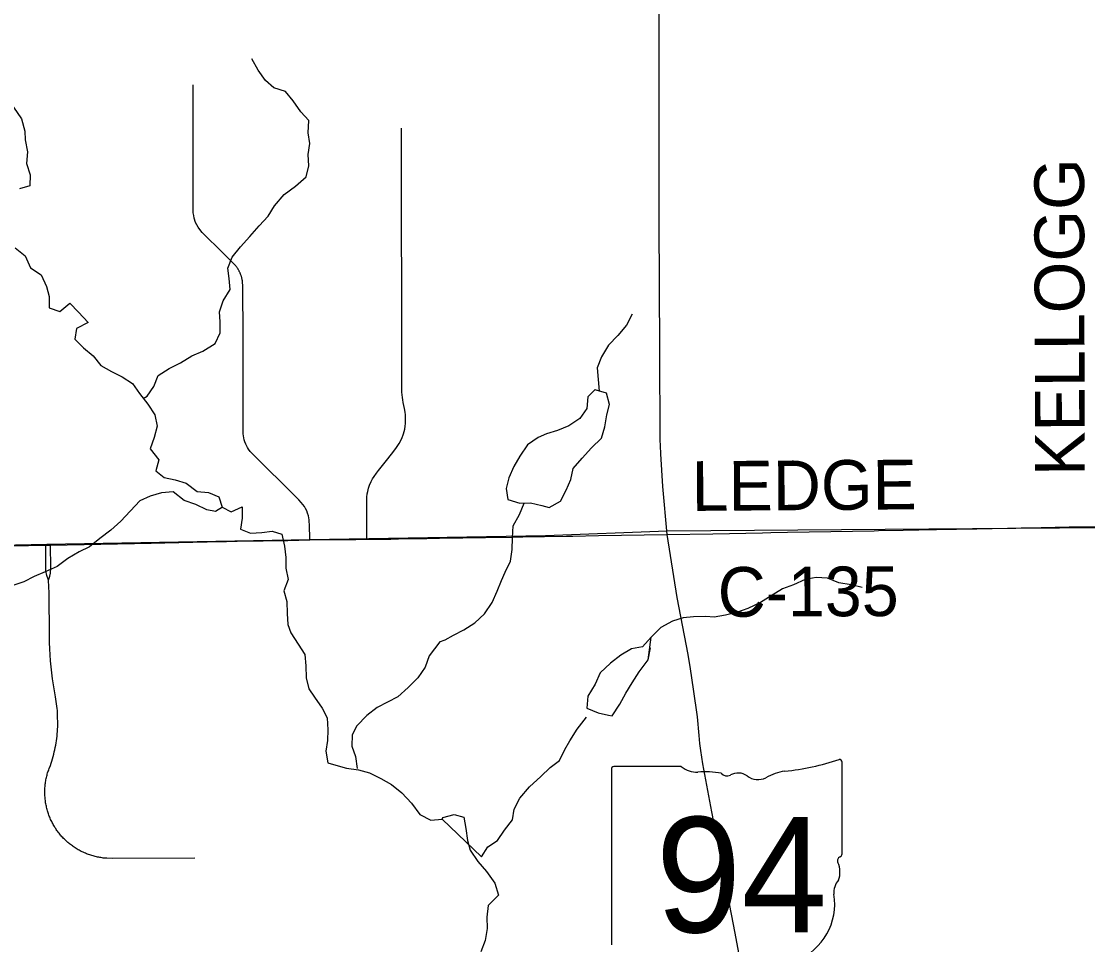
# Model space of a CAD drawing. Extents: x 0 to 34, y 0 to 22.
# Drawn here: x 4.171 to 5.39, y 18.6 to 19.655 of the extents above; entities that cross this region are included whole.
import ezdxf

# ---------------------------------------------------------------- set-up
doc = ezdxf.new("R2010")
doc.units = 0
for name, color, linetype in [('GM_X_Corporation', 7, 'Continuous'), ('GM_X_County_Road', 7, 'Continuous'), ('GM_X_County_Road_Text', 7, 'Continuous'), ('GM_X_Minor_Lake', 7, 'Continuous'), ('GM_X_Minor_River', 7, 'Continuous'), ('GM_X_State_Location', 7, 'Continuous'), ('GM_X_State_Route', 7, 'Continuous'), ('GM_X_State_Shield', 7, 'Continuous'), ('GM_X_Township_Road', 7, 'Continuous'), ('GM_X_Township_Road_Text', 7, 'Continuous')]:
    doc.layers.add(name, color=color, linetype=linetype)

msp = doc.modelspace()

# ---------------------------------------------------------------- linework, layer by layer
at = {"layer": 'GM_X_Corporation'}
msp.add_lwpolyline([(7.9922, 20.9), (2.8099, 20.9), (2.8107, 20.774), (2.8158, 19.9868), (2.8247, 19.0323), (3.279, 19.0395), (3.3208, 19.0402), (3.8964, 19.0508), (4.1999, 19.0575), (4.5008, 19.0629), (4.7704, 19.0672), (4.9094, 19.0728), (5.4081, 19.0763), (6.7986, 19.0964), (7.9898, 19.1149), (7.9901, 19.6615), (7.9904, 20.2824), (7.9906, 20.6512)], close=True, dxfattribs=at)
msp.add_lwpolyline([(2.837, 17.9259), (2.8293, 18.7154), (2.8247, 19.0323), (3.279, 19.0395), (3.3208, 19.0402), (3.8964, 19.0508), (4.1999, 19.0575), (4.5008, 19.0629), (4.7704, 19.0672), (4.9094, 19.0728), (5.4081, 19.0763), (6.7986, 19.0964), (7.9898, 19.1149), (7.9884, 19.0254), (7.988, 19.001), (7.9901, 18.1613), (7.991, 17.7727)], dxfattribs=at)
at = {"layer": 'GM_X_County_Road'}
msp.add_lwpolyline([(4.9092, 19.0685), (4.9614, 19.0694), (5.0183, 19.0704), (5.0278, 19.0706), (5.0471, 19.071), (5.0966, 19.0719), (5.1462, 19.0728), (5.1509, 19.0729), (5.1792, 19.0734), (5.197, 19.0738), (5.2172, 19.0742), (5.2634, 19.0751), (5.2987, 19.0757), (5.314, 19.076), (5.3369, 19.0765), (5.3692, 19.0771), (5.3849, 19.0774), (5.4163, 19.078)], dxfattribs=at)
at = {"layer": 'GM_X_Minor_Lake'}
for points in [[(4.8269, 19.234), (4.8262, 19.2335), (4.8186, 19.2259), (4.8175, 19.2126), (4.8095, 19.2011), (4.7969, 19.1928), (4.784, 19.1874), (4.7715, 19.1836), (4.762, 19.1794), (4.7498, 19.171), (4.7407, 19.1581), (4.7339, 19.1463), (4.7282, 19.1334), (4.7251, 19.1212), (4.7271, 19.1083), (4.7408, 19.1041), (4.7529, 19.1045), (4.7659, 19.1018)], [(4.8267, 19.2339), (4.8262, 19.2335), (4.8186, 19.2259), (4.8175, 19.2126), (4.8095, 19.2011), (4.7969, 19.1928), (4.784, 19.1874), (4.7715, 19.1836), (4.762, 19.1794), (4.7498, 19.171), (4.7407, 19.1581), (4.7339, 19.1463), (4.7282, 19.1334), (4.7251, 19.1212), (4.7271, 19.1083), (4.7408, 19.1041), (4.7529, 19.1045), (4.7659, 19.1018)], [(4.7659, 19.1018), (4.7746, 19.0992), (4.7872, 19.1064), (4.794, 19.119), (4.7993, 19.1312), (4.802, 19.1441), (4.8122, 19.1559), (4.8229, 19.1677), (4.8343, 19.1787), (4.838, 19.1917), (4.8403, 19.2054), (4.8433, 19.2172), (4.8399, 19.2301), (4.8267, 19.2339)], [(4.7659, 19.1018), (4.7746, 19.0992), (4.7872, 19.1064), (4.794, 19.119), (4.7993, 19.1312), (4.802, 19.1441), (4.8122, 19.1559), (4.8229, 19.1677), (4.8343, 19.1787), (4.838, 19.1917), (4.8403, 19.2054), (4.8433, 19.2172), (4.8399, 19.2301), (4.8269, 19.2339)], [(4.8909, 18.951), (4.881, 18.94), (4.8685, 18.9377), (4.8563, 18.9305), (4.8445, 18.9213), (4.8328, 18.9103), (4.8271, 18.8973), (4.8187, 18.8836), (4.8176, 18.87), (4.8305, 18.8646), (4.8422, 18.862)], [(4.8909, 18.951), (4.881, 18.94), (4.8685, 18.9377), (4.8563, 18.9305), (4.8445, 18.9213), (4.8328, 18.9103), (4.8271, 18.8973), (4.8187, 18.8836), (4.8176, 18.87), (4.8305, 18.8646), (4.8423, 18.862)], [(4.8422, 18.862), (4.8465, 18.8612), (4.8553, 18.8746), (4.8621, 18.8871), (4.8693, 18.8989), (4.8773, 18.9115), (4.8875, 18.9252), (4.8909, 18.951)], [(4.8423, 18.862), (4.8465, 18.8612), (4.8553, 18.8746), (4.8621, 18.8871), (4.8693, 18.8989), (4.8773, 18.9115), (4.8875, 18.9252), (4.8902, 18.9389)]]:
    msp.add_lwpolyline(points, dxfattribs=at)
at = {"layer": 'GM_X_Minor_River'}
for points in [[(4.3103, 19.2241), (4.3147, 19.2266), (4.3225, 19.2377), (4.3272, 19.2503), (4.3399, 19.2581), (4.353, 19.2648), (4.3657, 19.2726), (4.3785, 19.2782), (4.3923, 19.2868), (4.3982, 19.299), (4.3983, 19.3115), (4.3974, 19.3229), (4.4017, 19.3355), (4.4098, 19.3485), (4.4084, 19.361), (4.4071, 19.3728), (4.4118, 19.3854), (4.4214, 19.3973), (4.4322, 19.4093), (4.4426, 19.4212), (4.453, 19.4324), (4.4603, 19.4443), (4.4714, 19.457), (4.4845, 19.4667), (4.4964, 19.4772), (4.4996, 19.4901), (4.499, 19.503), (4.5007, 19.5156), (4.4989, 19.5277), (4.4995, 19.5417), (4.4906, 19.5518), (4.4817, 19.5642), (4.4728, 19.575), (4.4595, 19.579), (4.4499, 19.5875), (4.4417, 19.5995), (4.4343, 19.6123)], [(4.1618, 19.5571), (4.1711, 19.5436), (4.1747, 19.5296), (4.1753, 19.5197), (4.1778, 19.5061), (4.1769, 19.4925), (4.1809, 19.4796), (4.1804, 19.4671), (4.1687, 19.4635)], [(4.1638, 19.3962), (4.1753, 19.3869), (4.1813, 19.3734), (4.1935, 19.3652), (4.1994, 19.3521), (4.2026, 19.3404), (4.2025, 19.3275), (4.2147, 19.3235), (4.2262, 19.3328), (4.2362, 19.3227), (4.2474, 19.3108), (4.2339, 19.3041), (4.2319, 19.2919), (4.2419, 19.2818), (4.253, 19.2726), (4.2619, 19.2617), (4.2738, 19.2547), (4.286, 19.2488), (4.2978, 19.2411), (4.306, 19.2295), (4.3156, 19.2175), (4.3234, 19.2051), (4.3263, 19.1923), (4.3227, 19.1793), (4.3181, 19.1663), (4.3281, 19.154), (4.3245, 19.1414), (4.3341, 19.1336), (4.3467, 19.1311), (4.3592, 19.1272), (4.3719, 19.1175), (4.3848, 19.1163), (4.3966, 19.1115), (4.4006, 19.0998), (4.4109, 19.0943), (4.4232, 19.0999), (4.4235, 19.0873), (4.4214, 19.0744), (4.4329, 19.07), (4.4457, 19.0706), (4.4578, 19.0724), (4.4688, 19.0688), (4.4717, 19.0552), (4.4734, 19.0423), (4.4733, 19.0298), (4.4758, 19.0169), (4.4711, 19.0039), (4.4743, 18.9918), (4.4749, 18.9782), (4.4755, 18.9657), (4.4791, 18.9559)], [(4.8694, 19.3202), (4.863, 19.3077), (4.8531, 19.2959), (4.8421, 19.2848), (4.8341, 19.2715), (4.8292, 19.259), (4.8316, 19.2325)], [(4.4009, 19.0996), (4.3927, 19.0948), (4.3828, 19.0965), (4.3702, 19.1027), (4.3569, 19.1074), (4.3446, 19.1171), (4.331, 19.1161), (4.3183, 19.1121), (4.3062, 19.1069), (4.2847, 19.0838), (4.2732, 19.0733), (4.2605, 19.064), (4.2489, 19.0543), (4.2369, 19.0488), (4.2238, 19.041), (4.2119, 19.032), (4.198, 19.0257), (4.1856, 19.0206), (4.1736, 19.0143), (4.1612, 19.0103)], [(4.6491, 18.9456), (4.6554, 18.9481), (4.6649, 18.9534), (4.6767, 18.9595), (4.6896, 18.9675), (4.7006, 18.9778), (4.7094, 18.9907), (4.715, 19.0037), (4.72, 19.0158), (4.7241, 19.0254), (4.7302, 19.0379), (4.7321, 19.0512), (4.7325, 19.0645), (4.7332, 19.0782), (4.7404, 19.0912), (4.7457, 19.1041)], [(5.1324, 19.008), (5.1199, 19.011), (5.1058, 19.0133), (5.0929, 19.0186), (5.0799, 19.0193), (5.067, 19.017), (5.0537, 19.0109), (5.0411, 19.0064), (5.0282, 18.9984), (5.016, 18.9907), (5.0016, 18.9839), (4.9887, 18.9793), (4.9761, 18.9762), (4.9632, 18.9739), (4.9537, 18.9747), (4.9396, 18.9743), (4.9278, 18.9731), (4.9156, 18.9693), (4.9023, 18.9621), (4.8909, 18.951)], [(4.4791, 18.9559), (4.4873, 18.9431), (4.4951, 18.9311), (4.496, 18.9182), (4.4967, 18.9046), (4.4995, 18.8921), (4.5061, 18.8824), (4.5147, 18.87), (4.5205, 18.8587), (4.5215, 18.8451), (4.521, 18.8329), (4.5189, 18.8208), (4.5214, 18.8075), (4.5332, 18.8039), (4.5427, 18.8014), (4.5564, 18.7994), (4.5689, 18.7958), (4.5819, 18.7896), (4.5941, 18.7826), (4.606, 18.7733), (4.6168, 18.7614), (4.6265, 18.7483), (4.6391, 18.7417), (4.6519, 18.743)], [(4.6493, 18.9456), (4.6373, 18.9298), (4.6326, 18.9168), (4.6241, 18.9045), (4.613, 18.8937), (4.6014, 18.8829), (4.5895, 18.8766), (4.5778, 18.8707), (4.5659, 18.8614), (4.5544, 18.8498), (4.5493, 18.8395), (4.5487, 18.8266), (4.5531, 18.8145), (4.5549, 18.8009)], [(4.6519, 18.743), (4.6972, 18.6998), (4.7041, 18.7112), (4.7155, 18.7185), (4.7234, 18.7303), (4.7326, 18.7421), (4.7344, 18.7543), (4.7409, 18.7672), (4.7519, 18.7798), (4.7648, 18.7916), (4.7755, 18.8022), (4.7861, 18.8102), (4.7922, 18.8228), (4.7979, 18.8327), (4.8066, 18.846), (4.8172, 18.8597)], [(4.6519, 18.743), (4.653, 18.745), (4.6656, 18.7485), (4.677, 18.7454), (4.6793, 18.7325), (4.6812, 18.7188), (4.6839, 18.7074), (4.6927, 18.6945), (4.7026, 18.6831), (4.7121, 18.6698), (4.7163, 18.6561), (4.7045, 18.6443), (4.703, 18.631), (4.7034, 18.6181), (4.7012, 18.6044), (4.6963, 18.5915)]]:
    msp.add_lwpolyline(points, dxfattribs=at)
at = {"layer": 'GM_X_State_Route'}
for points in [[(4.9001, 19.5503), (4.9, 19.8066), (4.8997, 19.8309), (4.8996, 19.8655), (4.8992, 19.8959), (4.899, 19.9097), (4.8987, 19.9334), (4.8985, 19.9433), (4.8984, 19.9534), (4.8981, 19.9725), (4.8978, 20.0078), (4.8977, 20.0162), (4.8966, 20.1035)], [(4.9009, 19.2795), (4.9002, 19.4262), (4.9001, 19.5503)], [(4.9092, 19.0685), (4.9043, 19.1234), (4.902, 19.1607), (4.9017, 19.1698), (4.9014, 19.1767), (4.9009, 19.2795)], [(4.0993, 19.0542), (4.1987, 19.0561), (4.2043, 19.0562), (4.3194, 19.0587), (4.351, 19.0594), (4.3834, 19.06), (4.4054, 19.0605), (4.4177, 19.0607), (4.4474, 19.0612), (4.4757, 19.0617), (4.5006, 19.0623), (4.5365, 19.0626), (4.5534, 19.0628), (4.566, 19.063), (4.5824, 19.0631), (4.5935, 19.0633), (4.6022, 19.0634), (4.6261, 19.0638), (4.6347, 19.064), (4.6639, 19.0645), (4.6757, 19.0647), (4.6943, 19.065), (4.6998, 19.065)], [(4.6998, 19.065), (4.7016, 19.0651), (4.7323, 19.0656), (4.7398, 19.0657), (4.7442, 19.0658), (4.7942, 19.0666), (4.8014, 19.0667), (4.8308, 19.0672), (4.9092, 19.0685)], [(4.9952, 18.5704), (4.9926, 18.5841), (4.9873, 18.6125), (4.9789, 18.6561), (4.9743, 18.6804), (4.9604, 18.7515), (4.9502, 18.8063), (4.9479, 18.8214), (4.9469, 18.8297), (4.946, 18.8386), (4.9439, 18.8601), (4.9395, 18.8917), (4.9359, 18.9148), (4.9333, 18.9313), (4.9208, 18.9965), (4.9092, 19.0685)]]:
    msp.add_lwpolyline(points, dxfattribs=at)
at = {"layer": 'GM_X_State_Shield'}
for p, q in [((5.1093, 18.7034), (5.1093, 18.8081)), ((4.8457, 18.7997), (4.8457, 18.5995)), ((4.9255, 18.8031), (4.8482, 18.8031)), ((5.1093, 18.7034), (5.1093, 18.7034))]:
    msp.add_line(p, q, dxfattribs=at)
for centre, radius, start, end in [((5.0154, 19.0759), 0.2796, 275.8445, 288.9065), ((5.1064, 18.8085), 0.00294, 351.8621, 97.738), ((4.8487, 18.8001), 0.00305, 98.1301, 188.1301), ((4.9439, 18.8263), 0.0296, 231.6195, 271.1119), ((4.9537, 18.6907), 0.1064, 80.4867, 94.9883), ((4.9778, 18.8011), 0.00855, 219.7921, 297.1024), ((4.9904, 18.778), 0.0178, 54.4667, 119.1411), ((5.0133, 18.8097), 0.0214, 233.8562, 294.8282), ((5.0511, 18.742), 0.0563, 97.3462, 120.7689), ((5.1086, 18.6957), 0.00454, 107.944, 210.337), ((5.1062, 18.703), 0.00314, 289.6038, 7.7341), ((5.0797, 18.6825), 0.0273, 340.033, 23.6496), ((5.1198, 18.6596), 0.0198, 136.8065, 186.9296), ((5.0311, 18.6462), 0.0699, 292.3089, 8.9858)]:
    msp.add_arc(centre, radius, start, end, dxfattribs=at)
at = {"layer": 'GM_X_Township_Road'}
for points in [[(4.5006, 19.0623), (4.5002, 19.0802), (4.5001, 19.0824), (4.4999, 19.0851), (4.4996, 19.0875), (4.4991, 19.0898), (4.4982, 19.093), (4.4972, 19.0956), (4.4957, 19.0983), (4.4945, 19.1005), (4.491, 19.1051), (4.488, 19.1082), (4.4324, 19.1635), (4.4305, 19.1662), (4.4294, 19.1679), (4.4275, 19.1716), (4.4265, 19.1743), (4.4256, 19.1768), (4.4251, 19.179), (4.4247, 19.1812), (4.4244, 19.1835), (4.4243, 19.2947), (4.424, 19.3525), (4.4238, 19.3575), (4.4237, 19.3581), (4.4236, 19.3587), (4.4235, 19.3593), (4.4234, 19.3599), (4.4232, 19.3605), (4.4231, 19.3611), (4.423, 19.3617), (4.4228, 19.3623), (4.4226, 19.3629), (4.4224, 19.3635), (4.4223, 19.3641), (4.4221, 19.3647), (4.4219, 19.3653), (4.4216, 19.3659), (4.4214, 19.3664), (4.4212, 19.367), (4.4209, 19.3676), (4.4207, 19.3681), (4.4204, 19.3687), (4.4201, 19.3693), (4.4198, 19.3698), (4.4195, 19.3704), (4.4192, 19.3709), (4.4189, 19.3714), (4.4186, 19.3719), (4.4183, 19.3725), (4.4179, 19.373), (4.4176, 19.3735), (4.4172, 19.374), (4.4168, 19.3745), (4.4164, 19.375), (4.4161, 19.3755), (4.4157, 19.3759), (4.4153, 19.3764), (4.4148, 19.3769), (4.4144, 19.3773), (4.414, 19.3778), (4.4136, 19.3782), (4.4131, 19.3787), (4.4124, 19.3793), (4.4016, 19.3901), (4.3777, 19.4139), (4.3751, 19.4171), (4.3729, 19.42), (4.3714, 19.4226), (4.37, 19.4251), (4.3685, 19.43), (4.3679, 19.4331), (4.3675, 19.4362), (4.3674, 19.5827)], [(4.566, 19.063), (4.5659, 19.1084), (4.566, 19.1113), (4.5664, 19.115), (4.567, 19.1176), (4.5679, 19.1214), (4.5691, 19.125), (4.5709, 19.1291), (4.5725, 19.132), (4.5744, 19.1349), (4.5771, 19.1387), (4.5794, 19.1416), (4.5899, 19.155), (4.5969, 19.1639), (4.5998, 19.1679), (4.6028, 19.1725), (4.6058, 19.1783), (4.6077, 19.1835), (4.6092, 19.189), (4.6097, 19.1924), (4.61, 19.1954), (4.6102, 19.1986), (4.6101, 19.2051), (4.6096, 19.2085), (4.6089, 19.2127), (4.6083, 19.2161), (4.6076, 19.2195), (4.607, 19.2223), (4.6066, 19.225), (4.6062, 19.2283), (4.606, 19.2312), (4.6059, 19.2384), (4.6055, 19.5331)], [(4.2018, 19.0164), (4.1999, 19.0215), (4.1988, 19.0271), (4.1989, 19.0341), (4.1988, 19.052), (4.1987, 19.0561)], [(4.2018, 19.0164), (4.2035, 19.0207), (4.2041, 19.0242), (4.2044, 19.0302), (4.2043, 19.0562)], [(4.3692, 18.6984), (4.2746, 18.6979), (4.2685, 18.6983), (4.2672, 18.6984), (4.2658, 18.6985), (4.2645, 18.6986), (4.2632, 18.6988), (4.2619, 18.699), (4.2606, 18.6992), (4.2593, 18.6994), (4.258, 18.6997), (4.2567, 18.7), (4.2554, 18.7003), (4.2541, 18.7006), (4.2529, 18.7009), (4.2516, 18.7013), (4.2503, 18.7017), (4.2491, 18.7021), (4.2478, 18.7026), (4.2466, 18.703), (4.2454, 18.7035), (4.2441, 18.704), (4.2429, 18.7045), (4.2417, 18.7051), (4.2405, 18.7056), (4.2393, 18.7062), (4.2381, 18.7068), (4.237, 18.7075), (4.2358, 18.7081), (4.2347, 18.7088), (4.2336, 18.7095), (4.2324, 18.7102), (4.2313, 18.7109), (4.2302, 18.7116), (4.2292, 18.7124), (4.2281, 18.7132), (4.227, 18.714), (4.226, 18.7148), (4.225, 18.7156), (4.224, 18.7165), (4.223, 18.7174), (4.222, 18.7183), (4.221, 18.7192), (4.2201, 18.7201), (4.2191, 18.721), (4.2182, 18.722), (4.2173, 18.723), (4.2165, 18.7239), (4.2156, 18.7249), (4.2147, 18.726), (4.2139, 18.727), (4.2131, 18.728), (4.2123, 18.7291), (4.2115, 18.7302), (4.2108, 18.7313), (4.2101, 18.7324), (4.2093, 18.7335), (4.2086, 18.7346), (4.208, 18.7357), (4.2073, 18.7369), (4.2067, 18.7381), (4.2061, 18.7392), (4.2055, 18.7404), (4.2049, 18.7416), (4.2043, 18.7428), (4.2038, 18.744), (4.2033, 18.7452), (4.2028, 18.7465), (4.2023, 18.7477), (4.2019, 18.749), (4.2015, 18.7502), (4.2011, 18.7515), (4.2007, 18.7527), (4.2003, 18.754), (4.2, 18.7553), (4.1997, 18.7566), (4.1994, 18.7579), (4.1991, 18.7592), (4.1989, 18.7605), (4.1986, 18.7618), (4.1984, 18.7631), (4.1983, 18.7644), (4.1981, 18.7657), (4.198, 18.767), (4.1979, 18.7683), (4.1978, 18.7697), (4.1977, 18.771), (4.1978, 18.7789), (4.1979, 18.7802), (4.1981, 18.7815), (4.1982, 18.7829), (4.1984, 18.7842), (4.1986, 18.7855), (4.1988, 18.7868), (4.199, 18.7881), (4.1993, 18.7894), (4.1996, 18.7907), (4.1999, 18.792), (4.2002, 18.7933), (4.2005, 18.7945), (4.2009, 18.7958), (4.2013, 18.7971), (4.2017, 18.7983), (4.2022, 18.7996), (4.2026, 18.8008), (4.204, 18.8045), (4.2048, 18.807), (4.2056, 18.8095), (4.2064, 18.8121), (4.2071, 18.8146), (4.2078, 18.8172), (4.2084, 18.8198), (4.209, 18.8223), (4.2096, 18.8249), (4.2101, 18.8275), (4.2105, 18.8301), (4.2109, 18.8327), (4.2113, 18.8354), (4.2116, 18.838), (4.2119, 18.8406), (4.2121, 18.8433), (4.2122, 18.8459), (4.2124, 18.8486), (4.2125, 18.8512), (4.2123, 18.8618), (4.2122, 18.8644), (4.212, 18.8671), (4.2118, 18.8697), (4.2115, 18.8723), (4.2111, 18.875), (4.2108, 18.8776), (4.2103, 18.8802), (4.2099, 18.8828), (4.2075, 18.8965), (4.2065, 18.9033), (4.2057, 18.9102), (4.2049, 18.9171), (4.2043, 18.9241), (4.2038, 18.931), (4.2034, 18.9379), (4.2031, 18.9449), (4.203, 18.9518), (4.2026, 19.0016), (4.2024, 19.0086), (4.2018, 19.0164)]]:
    msp.add_lwpolyline(points, dxfattribs=at)

# ---------------------------------------------------------------- texts
at = {"layer": 'GM_X_County_Road_Text'}
for s, rotation, p in [('LEDGE', 0.4195, (4.9375, 19.0954)), ('C-135', 0.2753, (4.9673, 18.9743))]:
    msp.add_text(s, height=0.05682, rotation=rotation, dxfattribs=at).set_placement(p)
at = {"layer": 'GM_X_State_Location'}
for s in ['s', 'r']:
    msp.add_text(s, height=0.000189, dxfattribs=at).set_placement((4.9745, 18.6863))
msp.add_text('94', height=0.000189, rotation=0, dxfattribs=at).set_placement((4.9268, 18.6725))
at = {"layer": 'GM_X_State_Shield'}
msp.add_text('94', height=0.13184, dxfattribs=at).set_placement((4.8962, 18.6136))
at = {"layer": 'GM_X_Township_Road_Text'}
msp.add_text('KELLOGG', height=0.05682, rotation=90.1463, dxfattribs=at).set_placement((5.387, 19.1355))

doc.saveas('drawing.dxf')
